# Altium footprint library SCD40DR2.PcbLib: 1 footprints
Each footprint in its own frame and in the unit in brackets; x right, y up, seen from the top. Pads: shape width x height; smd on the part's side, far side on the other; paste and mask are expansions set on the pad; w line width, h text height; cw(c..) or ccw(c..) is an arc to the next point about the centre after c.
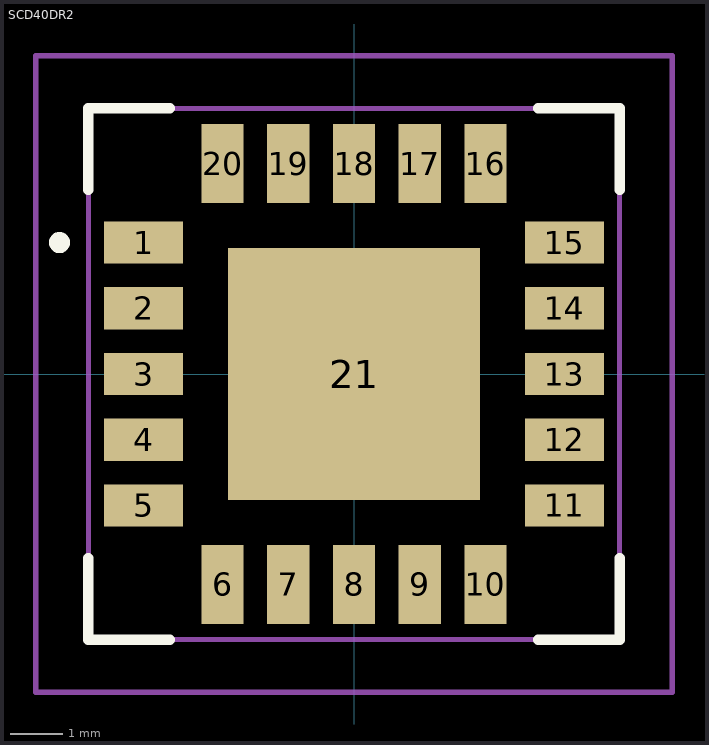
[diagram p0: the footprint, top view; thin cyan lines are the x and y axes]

## SCD40DR2 [mm]
pads (21):
  rect 1.5x0.8 smd: 1(-4,2.5) 2(-4,1.25) 3(-4,0) 4(-4,-1.25) 5(-4,-2.5) 11(4,-2.5) 12(4,-1.25) 13(4,0) 14(4,1.25) 15(4,2.5)
  rect 0.8x1.5 smd: 6(-2.5,-4) 7(-1.25,-4) 8(0,-4) 9(1.25,-4) 10(2.5,-4) 16(2.5,4) 17(1.25,4) 18(0,4) 19(-1.25,4) 20(-2.5,4)
  rect 4.8x4.8 smd: 21(0,0)
Top Overlay:
  lines w0.2: -5.05,-3.5 -5.05,-5.05 -3.5,-5.05 ; -5.05,3.5 -5.05,5.05 -3.5,5.05 ; 3.5,-5.05 5.05,-5.05 5.05,-3.5 ; 3.5,5.05 5.05,5.05 5.05,3.5 ; -5.6,2.4 -5.6,2.4 ; -5.6,2.4 ccw(c-5.6,2.5) -5.6,2.6 ; -5.6,2.4 cw(c-5.6,2.5) -5.6,2.6 ; -5.6,2.6 -5.6,2.6
Mechanical 15:
  lines w0.1: -5.05,-5.05 5.05,-5.05 5.05,5.05 -5.05,5.05 -5.05,-5.05
Mechanical 20:
  lines w0.1: -6.05,-6.05 6.05,-6.05 6.05,6.05 -6.05,6.05 -6.05,-6.05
